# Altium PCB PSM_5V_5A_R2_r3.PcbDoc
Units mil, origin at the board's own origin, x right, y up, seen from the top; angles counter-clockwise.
Board outline 1350 x 1700 mil, 2 copper layers (Top Layer, Bottom Layer), stack 62 mil thick; 44 components, 17 nets, 129 pads, 76 vias.
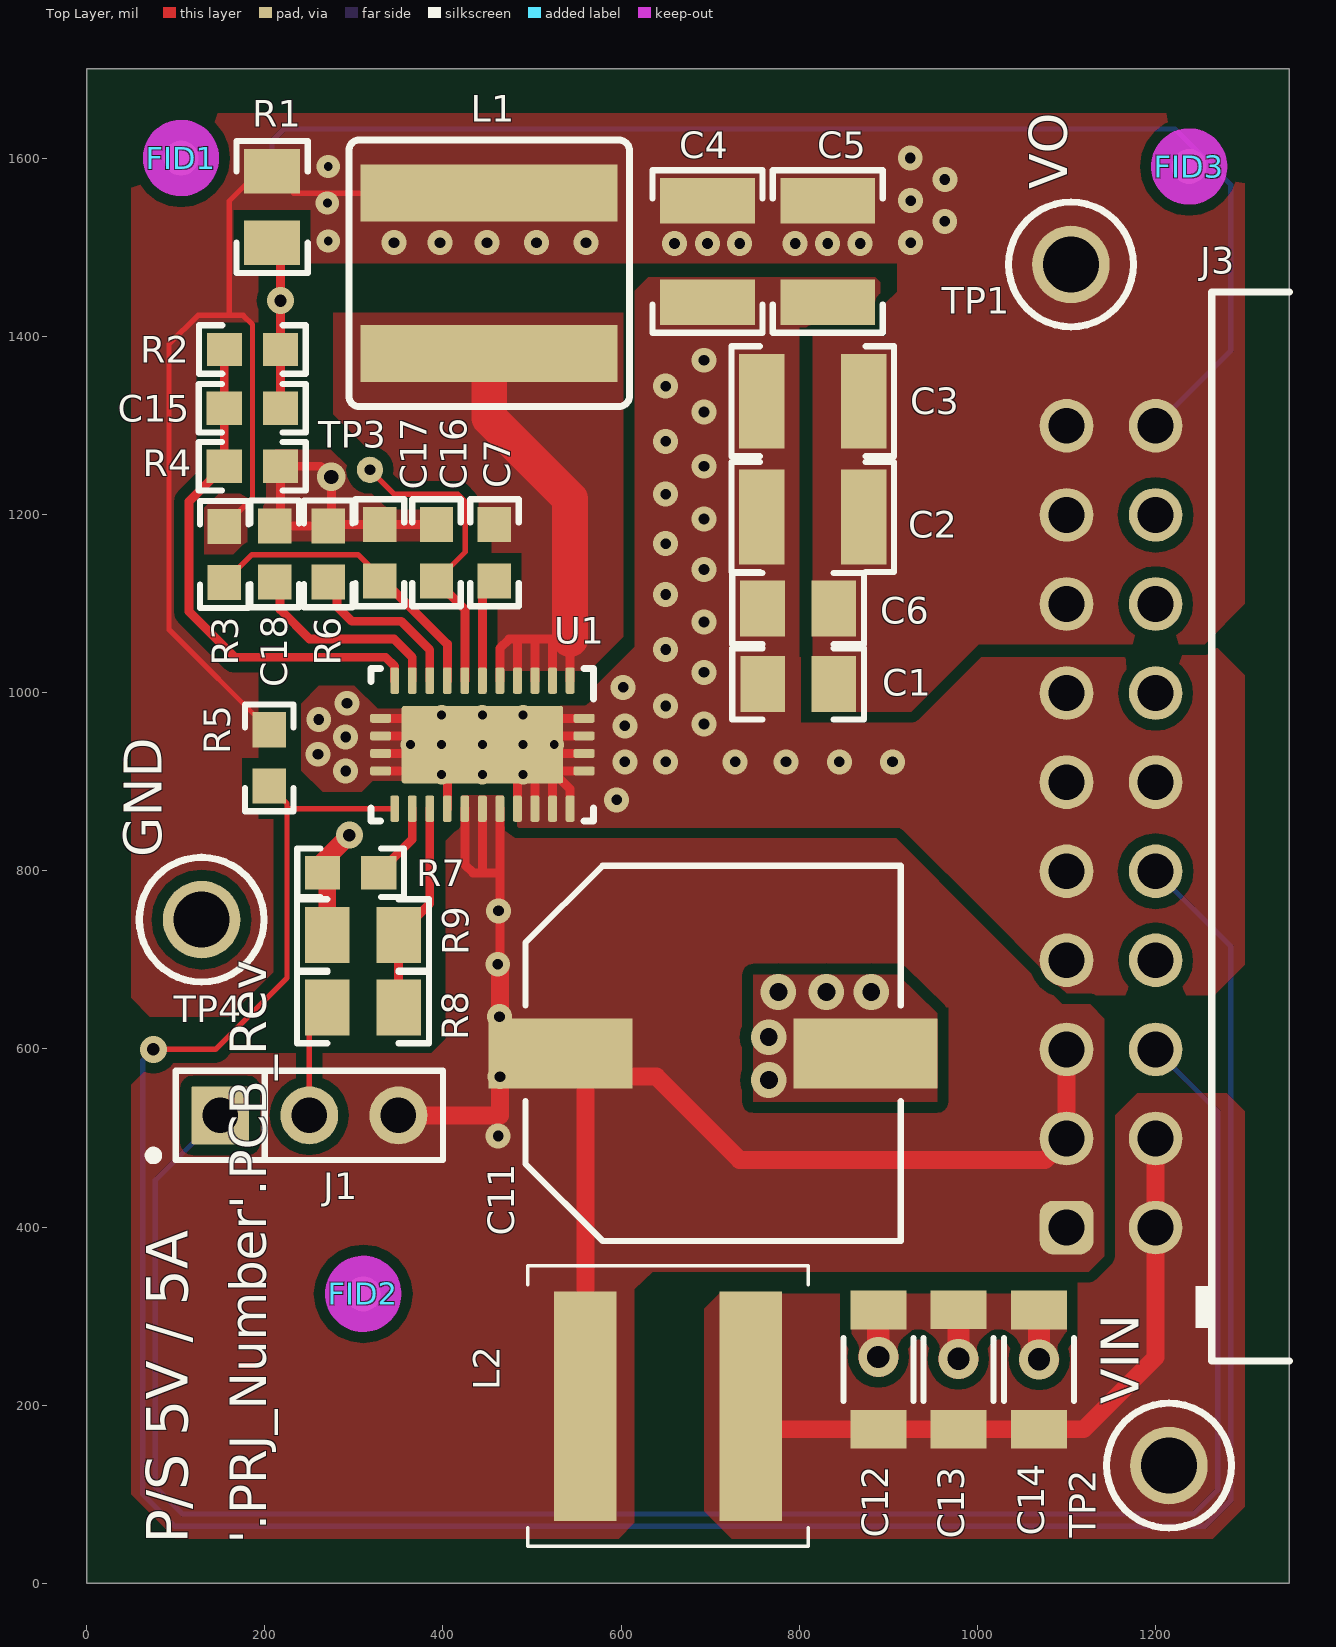
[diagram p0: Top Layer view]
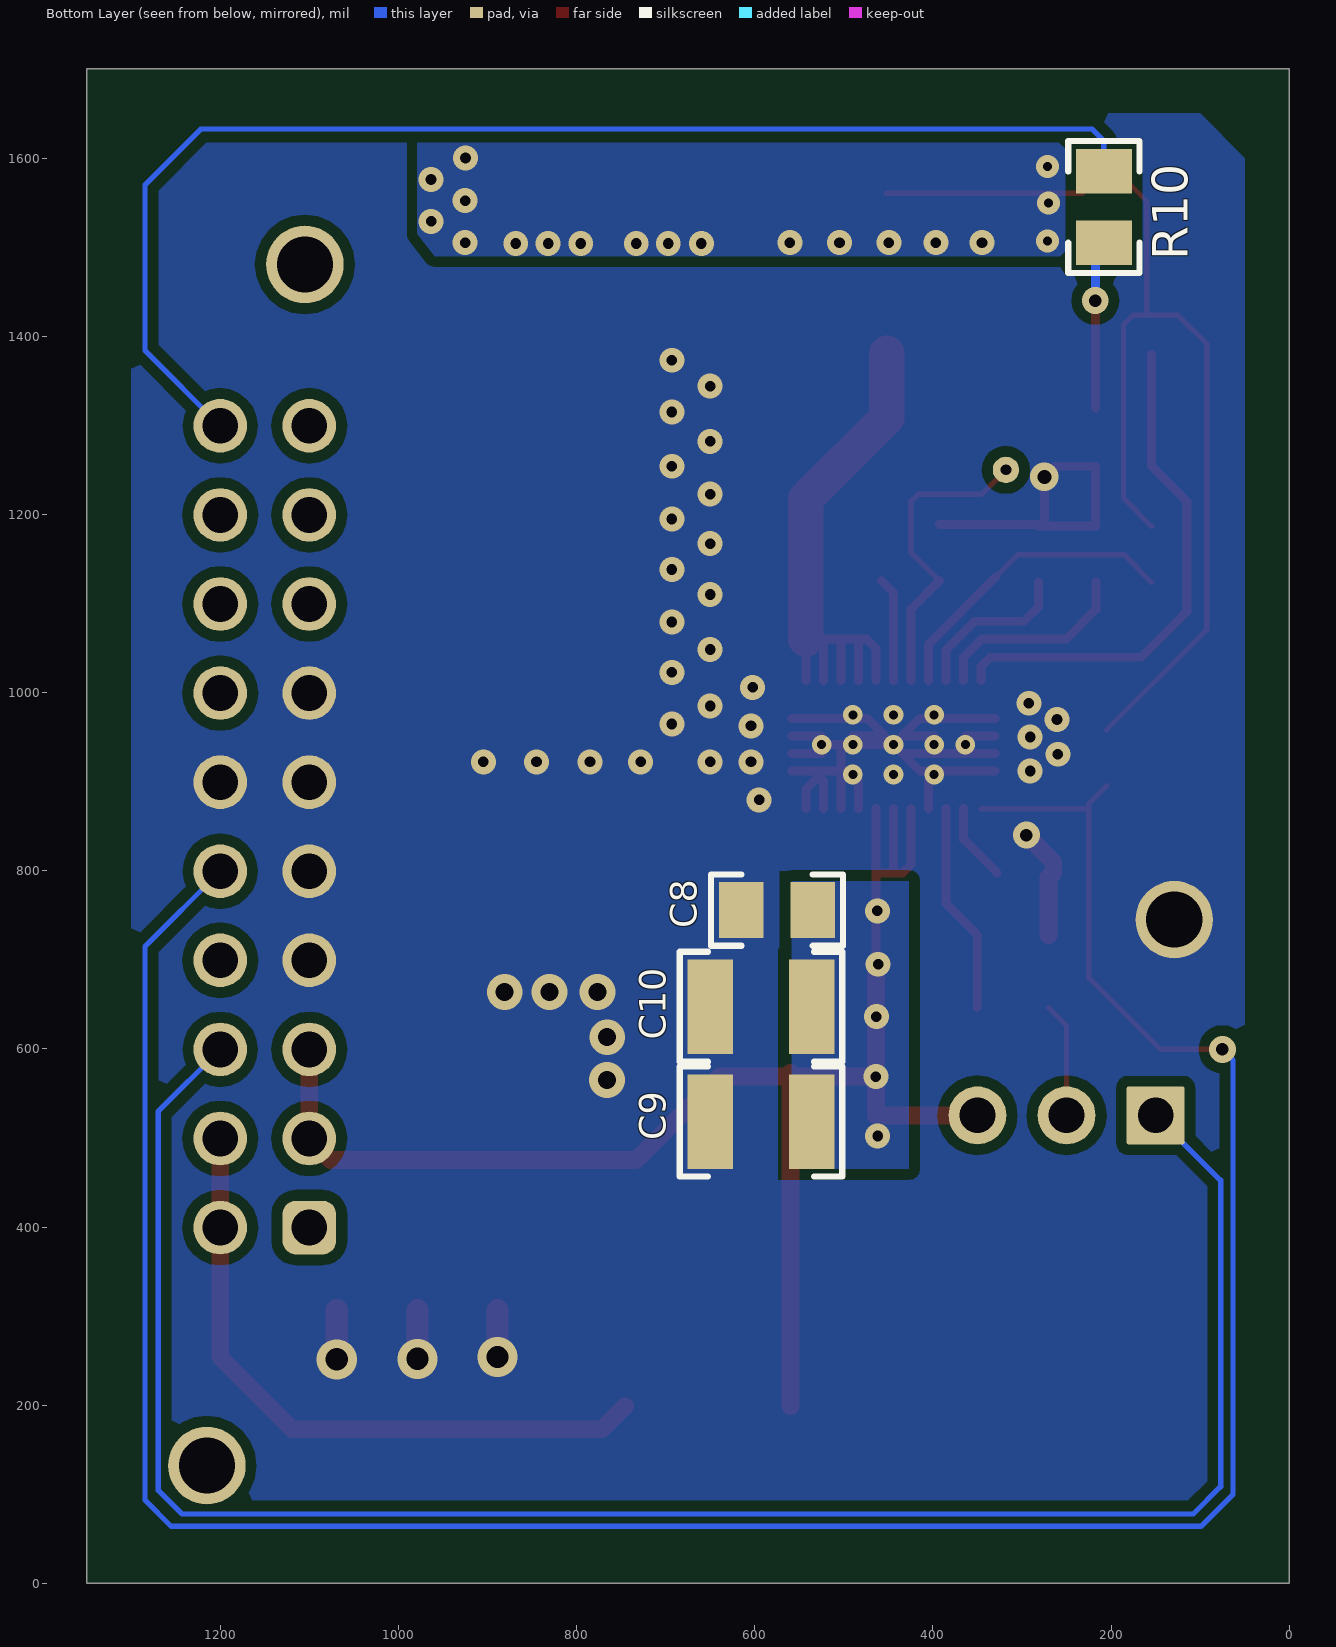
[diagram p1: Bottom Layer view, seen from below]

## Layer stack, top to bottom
Top Solder: solder mask 0.4, Solder Resist, Dk 3.5
Top Layer: signal copper 2.8
Dielectric1: core 56.4, FR-4, Dk 4.8
Bottom Layer: signal copper 2.8
Bottom Solder: solder mask 0.4, Solder Resist, Dk 3.5

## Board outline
0,0 1350,0 1350,1700 0,1700

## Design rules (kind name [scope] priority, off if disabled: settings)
AcuteAngle [All] p1: minimum=4.50000000000000E+0001 checktracksonly=FALSE
AssemblyTestPointUsage [All] p1: valid=2
BoardOutlineClearance BoardOutlineClearance_MountingHoles [OnCopper and InComponentClass('Mounting Holes')] p1: gap=39.37 ignorepadtopadclearanceinfootprint=FALSE
BoardOutlineClearance BoardOutlineClearance_Poly [OnCopper and IsPoly] p2: gap=25 ignorepadtopadclearanceinfootprint=FALSE
BoardOutlineClearance [OnCopper and Not InComponentClass('Logo') and not InComponentClass('FiducialMark') and not InRegion(1000,500,4000,800) and not InPoly] p3: gap=60 ignorepadtopadclearanceinfootprint=FALSE
Clearance Clearance_Keepouts [((IsTrack Or IsArc) And Not InPoly) And IsFree and IsKeepOut vs ((IsTrack Or IsArc) And Not InPoly) And IsFree and IsKeepOut] p1: gap=0 ignorepadtopadclearanceinfootprint=FALSE
Clearance Clearance_Poly [InPolygon] p2: gap=12 ignorepadtopadclearanceinfootprint=TRUE
Clearance Clearance_FiducialMark [IsKeepOut and InComponentClass('FiducialMark') vs IsPad and InComponentClass('FiducialMark')] p3: gap=0 ignorepadtopadclearanceinfootprint=FALSE
Clearance [All] p4: gap=7.87 ignorepadtopadclearanceinfootprint=TRUE
ComponentClearance ComponentClearance_MountingHoles_FiducialMarks [InComponentClass('Mounting Holes') vs InComponentClass('FiducialMark')] p1: gap=50 collisioncheckmode=3 verticalgap=10 showdistances=FALSE
ComponentClearance ComponentClearance_Shunt [InComponentClass('Header') vs InComponentClass('Shunt')] p2: gap=0 collisioncheckmode=3 verticalgap=0 showdistances=FALSE
ComponentClearance ComponentClearance_Logo [InComponentClass('Logo')] p3: gap=50 collisioncheckmode=3 verticalgap=10 showdistances=FALSE
ComponentClearance ComponentClearance_ScrewToNut [(HasFootprint('NY PMS 440 0025 PH')) vs (HasFootprint('Keystone_1902C'))] p4: gap=5 collisioncheckmode=3 verticalgap=10 showdistances=FALSE
ComponentClearance ComponentClearance_MountingHoles [InComponentClass('Mounting Holes')] p5: gap=250 collisioncheckmode=3 verticalgap=100000 showdistances=FALSE
ComponentClearance ComponentClearance_SmallPassives [HasFootprint('0201*') or HasFootprint('0402*') or HasFootprint('0508') or HasFootprint('0603*') or HasFootprint('0612') or HasFootprint('0805*') or HasFootprint('0815*') or HasFootprint('0830*') or HasFootprint('1206*') or HasFootprint('1210*') or HasFootprint('1808*') or HasFootprint('1812*') or HasFootprint('1825*') or HasFootprint('2010*') or HasFootprint('2220*') or HasFootprint('2225*') or HasFootprint('2512*') or HasFootprint('2728*') or HasFootprint('3518*') vs HasFootprint('0201*') or HasFootprint('0402*') or HasFootprint('0508') or HasFootprint('0603*') or HasFootprint('0612') or HasFootprint('0805*') or HasFootprint('0815*') or HasFootprint('0830*') or HasFootprint('1206*') or HasFootprint('1210*') or HasFootprint('1808*') or HasFootprint('1812*') or HasFootprint('1825*') or HasFootprint('2010*') or HasFootprint('2220*') or HasFootprint('2225*') or HasFootprint('2512*') or HasFootprint('2728*') or HasFootprint('3518*')] p6: gap=14.96 collisioncheckmode=3 verticalgap=10 showdistances=FALSE
ComponentClearance ComponentClearance_THtoSMT [IsThruComponent vs IsSMTComponent] p7: gap=40 collisioncheckmode=3 verticalgap=30 showdistances=FALSE
ComponentClearance ComponentClearance_THtoTH [IsThruComponent vs IsThruComponent] p8: gap=30 collisioncheckmode=3 verticalgap=30 showdistances=FALSE
ComponentClearance [All] p9: gap=30 collisioncheckmode=3 verticalgap=10 showdistances=FALSE
DiffPairsRouting [All] p1: maxlimit=100 minlimit=10 mostfreqgap=10 toplayer_minwidth=15 toplayer_maxwidth=15 toplayer_prefwidth=15 bottomlayer_minwidth=15 bottomlayer_maxwidth=15 bottomlayer_prefwidth=15 maxuncoupledlength=1000
FabricationTestPointUsage TestPointUsage [All] p1: valid=2 allowmultiple=FALSE
FabricationTestpoint Testpoint [All] p1: side=3 testpointundercomponent=TRUE minsize=40 maxsize=100 preferedsize=60 minholesize=0 maxholesize=40 preferedholesize=32 testpointgrid=1 allowsidetop=TRUE allowsidebottom=TRUE usegrid=TRUE gridtolerance=0.01
FanoutControl Fanout_LCC [IsLCC] p1: bgadir=Out bgaviamode=Centered fanoutstyle=Auto fanoutdirection=Alternating viagrid=1 // Fanout_LCC (Default Rule)
FanoutControl Fanout_BGA [IsBGA] p2: bgadir=Out bgaviamode=Centered fanoutstyle=Auto fanoutdirection=Alternating viagrid=1 // Fanout_BGA (Default Rule)
FanoutControl Fanout_Default [All] p4: bgadir=Out bgaviamode=Centered fanoutstyle=Auto fanoutdirection=Alternating viagrid=1 // Fanout_Default (Default Rule)
FanoutControl Fanout_Small [(CompPinCount < 5)] p5: bgadir=Out bgaviamode=Centered fanoutstyle=Auto fanoutdirection=OutThenIn viagrid=1 // Fanout_Small (Default Rule)
HoleSize [All] p1: absolutevalues=TRUE maxlimit=251 minlimit=7.87 maxpercent=80.000 minpercent=20.000
MinimumAnnularRing MinimumAnnularRing_ThermalPadVias [IsVia and InAnyComponent] p1: minimumring=5.91
MinimumAnnularRing [All] p2: minimumring=7.87
MinimumSolderMaskSliver MinimumSolderMaskSliver_Logo [InComponentClass('Logo') vs InComponentClass('Logo')] p1: minsoldermaskwidth=0.7
MinimumSolderMaskSliver [All] p2: minsoldermaskwidth=3.94
PlaneConnect [All] p1: planeconnectstyle=Relief reliefexpansion=10 reliefentries=4 reliefconductorwidth=10 reliefairgap=10
PolygonConnect [All] p1: connectstyle=Direct reliefconductorwidth=10 reliefentries=4 polygonreliefangle="90 Angle" airgapwidth=10
RoutingVias ThermalPadVias [IsVia and InAnyComponent] p1: holewidth=7.87 width=19.68 viastyle="Through Hole" minholewidth=7.87 minwidth=19.68 maxholewidth=12.99 maxwidth=23.62
RoutingVias [All] p2: holewidth=16 width=34 viastyle="Through Hole" minholewidth=7.87 minwidth=26 maxholewidth=40 maxwidth=65
SilkToBoardRegionClearance [Not ((IsComment or IsDesignator) And (Hide <> 'False')) and not InRegion(1000,500,4000,800)] p1:
SilkToSilkClearance SilkToSilkClearance_Pb-FreeLogo [(HasFootprint('Pb-Free_Overlay_Medium') OR HasFootprint('Pb-Free_Overlay_Small')) vs (HasFootprint('Pb-Free_Overlay_Medium') OR HasFootprint('Pb-Free_Overlay_Small'))] p1: silktosilkclearance=0
SilkToSilkClearance [All] p2: silktosilkclearance=3.94
SilkToSolderMaskClearance SilkToComponentPadClearance [(IsPad or IsFill or IsRegion) and InAnycomponent] p1: minsilkscreentomaskgap=5 clearancetoexposedcopper=TRUE
SilkToSolderMaskClearance "Silk to Solder Mask Opening" [All] p2: minsilkscreentomaskgap=3.94 clearancetoexposedcopper=FALSE
SolderMaskExpansion [All] p1: expansion=1.97
UnRoutedNet [All] p1: checkbadconnections=TRUE
Width [All] p1: maxlimit=100 minlimit=6 preferedwidth=10 checkconnectedcopper=TRUE
14 further rules are at their usual default settings.

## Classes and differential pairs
component class Header: J1 J6 J7
component class FiducialMark: FID1 FID2 FID3
component class AssemblyNote: ZZ1 ZZ2 ZZ3 ZZ4

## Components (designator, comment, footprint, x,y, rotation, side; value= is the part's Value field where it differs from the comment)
C1 "Capacitor" 0805_HV 798.79,1009.69 r0 top value=0.47uF
C2 "Capacitor" 1210_270 815.05,1197.07 r180 top value=22uF
C3 "Capacitor" 1210_270 815.05,1326.91 r180 top value=22uF
C4 "Capacitor" 1210_270 697.07,1495.02 r270 top value=22uF
C5 "Capacitor" 1210_270 831.91,1495.02 r270 top value=22uF
C6 "Capacitor" 0805_HV 798.72,1094.31 r0 top value=0.47uF
C7 "Capacitor" 0603 457.73,1156.92 r270 top value=0.47uF
C8 "Capacitor" 0805_HV 575,755.84 r180 bottom value=0.47uF
C9 "Capacitor" 1210_270 592.91,518.37 r180 bottom value=10uF
C10 "Capacitor" 1210_270 592.91,647.24 r180 bottom value=10uF
C11 "Cap_Polarized" SM_RADIAL_G 703.2,595 r0 top value=100uF
C12 "Capacitor" 1206_180 888.78,240 r90 top value=2.2uF
C13 "Capacitor" 1206_180 978.61,240.04 r90 top value=2.2uF
C14 "Capacitor" 1206_180 1069.2,240 r90 top value=2.2uF
C15 "Capacitor" 0603 186,1319.13 r180 top value=4.7pF
C16 "Capacitor" 0603 392.73,1156.92 r90 top value=2.2uF
C17 "Capacitor" 0603 329.24,1156.92 r90 top value=1uF
C18 "Capacitor" 0603 211.11,1155.66 r90 top value=0.01uF
FID1 "Fiducial" Fiducial10-20 106.02,1600 r0 top
FID2 "Fiducial" Fiducial10-20 310.59,325 r0 top
FID3 "Fiducial" Fiducial10-20 1237.59,1590.47 r0 top
J1 "Header_3x1" Samtec_HTSW-103-07-G-S 249.99,525.37 r0 top
J3 "SFH11-PBPC-D10-RA-BK" Sullins_SFH11-xxxC-D10-RA 1150,849.41 r90 top
L1 "Inductor_Iron" XAL7070 451.88,1470.62 r90 top value=6.8uH
L2 "Inductor_Iron" XAL7030 652.81,198.94 r0 top value=2.2uH
R1 "Resistor" 0805_HV 208.13,1545 r90 top value=100
R2 "Resistor" 0603 186.15,1385 r0 top value=100k
R3 "Resistor" 0603 154.5,1155 r270 top value=0
R4 "Resistor" 0603 186,1254.04 r180 top value=24.9k
R5 "Resistor" 0603 205,926.73 r270 top value=100k
R6 "Resistor" 0603 271.3,1155.66 r90 top value=100k
R7 "Resistor" 0603 296.41,797.56 r0 top value=100
R8 "RG2012P-222-B-T5" 0805_HV 310.22,646.37 r180 top value=2.20k
R9 "Resistor" 0805_HV 310.22,727.98 r0 top value=121k
R10 "Resistor" 0805_HV 208.13,1545 r90 bottom value=100
TP1 "5013" Keystone5013 1105,1480.52 r0 top
TP2 "5010" Keystone5010 1215,132.3 r0 top
TP3 "TP_H0.45P0.75" TP_H045P075 318.06,1250 r0 top
TP4 "5010" Keystone5010 129.09,745.07 r0 top
U1 "LM73605QRNPRQ1" RNP0030A 444.26,941.47 r270 top
ZZ1 "This Assembly Note is for PCB labels only" AssemblyNoteLabel 185,2313 r0 top
ZZ2 "These assemblies are ESD sensitive, ESD precautions shall be observed." AssemblyNote 185,2204.11 r0 top
ZZ3 "These assemblies must be clean and free from flux and all contaminants. Use of no clean flux is not acceptable." AssemblyNote 185,2115.56 r0 top
ZZ4 "These assemblies must comply with workmanship standards IPC-A-610 Class 2, unless otherwise specified." AssemblyNote 185,2027 r0 top

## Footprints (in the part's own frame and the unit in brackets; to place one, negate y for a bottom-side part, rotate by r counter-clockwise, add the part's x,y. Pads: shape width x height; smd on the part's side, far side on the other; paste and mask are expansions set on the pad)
0603 [mm] "0603 from SM-752 data"
  rect 1x0.95 smd: 1(-0.8,0) 2(0.8,0)
  silkscreen extent -1.52,-0.69 1.52,0.69, body extent -0.87,-0.47 0.87,0.47, height 1
0805_HV [mil] "0805 with 30mil clearance between pads"
  rect 50x63 smd: 1(-40,0) 2(40,0)
  silkscreen extent -74,-40 74,40, body extent -43,-29 43,29, height 57
1206_180 [mm] "1206_180"
  rect 1.1x1.6 smd: 1(-1.7,0) 2(1.7,0)
  silkscreen extent -0.9,-1 0.9,1, body extent -1.75,-0.95 1.75,0.95, height 1.8
1210_270 [mm] "1210"
  rect 1.3x2.7 smd: 1(-1.45,0) 2(1.45,0)
  silkscreen extent -2.32,-1.57 2.32,1.57, body extent -1.7,-1.35 1.7,1.35, height 2.7
AssemblyNote [mil] "Assembly Note"
AssemblyNoteLabel [mil] "Assembly Note for PCB Labels"
Fiducial10-20 [mm]
  round 1 smd mask+0.5: 1(0,0)
  Top Layer keep-out circle w1.178: c0,0 r0.5
Keystone5010 [mil] "Keystone Multipurpose loops"
  round 87 hole 63: 1(0,0)
  silkscreen extent -70,-70 70,70, body extent -63,-63 63,62, height 319
Keystone5013 [mil] "Keystone Multipurpose loops"
  round 87 hole 63: 1(0,0)
  silkscreen extent -70,-70 70,70, body extent -63,-63 63,62, height 319
RNP0030A [mm] "QFN, 30-Leads, Body 6x4mm, Pitch 0.5mm, Thermal Pad 4.6x2.2mm"
  rrect40% 0.75x0.25 smd: 1(-1.825,2.5) 2(-1.825,2) 3(-1.825,1.5) 4(-1.825,1) 5(-1.825,0.5) 6(-1.825,0) 7(-1.825,-0.5) 8(-1.825,-1) 9(-1.825,-1.5) 10(-1.825,-2) 11(-1.825,-2.5) 16(1.825,-2.5) 17(1.825,-2) 18(1.825,-1.5) 19(1.825,-1) 20(1.825,-0.5) 21(1.825,0) 22(1.825,0.5) 23(1.825,1) 24(1.825,1.5) 25(1.825,2) 26(1.825,2.5)
  rrect40% 0.25x0.6 smd: 12(-0.75,-2.9) 13(-0.25,-2.9) 14(0.25,-2.9) 15(0.75,-2.9) 27(0.75,2.9) 28(0.25,2.9) 29(-0.25,2.9) 30(-0.75,2.9)
  rrect5% 2.2x4.6 smd paste-3: 31(0,0)
  rrect10% 0.98x0.96 on Top Paste: 31A(-0.59,1.74) 31A(-0.59,0.58) 31A(-0.59,-0.58) 31A(-0.59,-1.74) 31A(0.59,1.74) 31A(0.59,0.58) 31A(0.59,-0.58) 31A(0.59,-1.74)
  silkscreen extent -2.17,-3.17 2.17,3.18, body extent -2,-3 2,3, height 0.77
Samtec_HTSW-103-07-G-S [mm] "Samtec 100mil, 1x3, 230 mil above insulator"
  rrect6% 1.65x1.65 hole 1.016: 1(-2.54,0)
  round 1.65 hole 1.016: 2(0,0) 3(2.54,0)
  silkscreen extent -4.57,-1.27 3.81,1.27, body extent -3.81,-1.27 3.81,1.27, height 8.38
SM_RADIAL_G [mm] "10 x 10.2mm:  Panasonic G"
  rect 4.1x2 smd: 1(-4.35,0) 2(4.35,0)
  silkscreen extent -5.35,-5.35 5.35,5.35, body extent -5.25,-5.25 5.25,5.25, height 10.5
Sullins_SFH11-xxxC-D10-RA [mm] "Receptacle, 2.54mm, 10x2, R/A, TH"
  rrect50% 1.53x1.53 hole 1.02: 1(-11.43,1.27)
  round 1.53 hole 1.02: 2(-11.43,-1.27) 3(-8.89,1.27) 4(-8.89,-1.27) 5(-6.35,1.27) 6(-6.35,-1.27) 7(-3.81,1.27) 8(-3.81,-1.27) 9(-1.27,1.27) 10(-1.27,-1.27) 11(1.27,1.27) 12(1.27,-1.27) 13(3.81,1.27) 14(3.81,-1.27) 15(6.35,1.27) 16(6.35,-1.27) 17(8.89,1.27) 18(8.89,-1.27) 19(11.43,1.27) 20(11.43,-1.27)
  silkscreen extent -15.24,-5.08 15.24,-2.4, body extent -15.24,-11.37 15.24,1.47, height 7
TP_H045P075 [mm] "TP_H0.45P0.75"
  round 0.75 hole 0.305: 1(0,0)
XAL7030 [mm] "Coilcraft XAL7030 7.5 x.7.5 x 3.1 mm"
  rect 1.78x6.55 smd: 1(-2.36,0) 2(2.36,0)
  silkscreen extent -4,-4 4,4, body extent -4,-4 4,4, height 3.1
XAL7070 [mm] "COILCRAFT"
  rect 1.63x7.33 smd: 1(-2.285,0) 2(2.285,0)
  silkscreen extent -3.8,-4 3.8,4, body extent -3.8,-4 3.8,4, height 7

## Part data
C1 C6 C8: library part CMP-0008357-2, "CAP, CERM, 0.47 uF, 50 V, +/- 10%, X7R, 0805", Cap_Case=0805, Manufacturer=MuRata, PartNumber=GRM21BR71H474KA88L, Supplier Part Number 1=490-3328-1-ND, TempCo=X7R, Tolerance_%=10%, Value1=Unknown, Value2=50V, ValueDisplayed=0.47uF
C2 C3 C4 C5: library part CMP-0009222-2, "CAP, CERM, 22 uF, 16 V, +/- 10%, X7R, 1210", Cap_Case=1210, Manufacturer=MuRata, PartNumber=GRM32ER71C226KE18L, Supplier Part Number 1=490-4524-1-ND, TempCo=X7R, Tolerance_%=10%, Value1="0.003 ohm", Value2=16V, ValueDisplayed=22uF
C7: library part CMP-0007346-5, "CAP, CERM, 0.47 uF, 25 V, +/- 10%, X5R, 0603", Cap_Case=0603, Manufacturer=MuRata, PartNumber=GRM188R61E474KA12D, Supplier Part Number 1=GRM188R61E474KA12D-ND, TempCo=X5R, Tolerance_%=10%, Value1=Unknown, Value2=25V, ValueDisplayed=0.47uF
C9 C10: library part CMP-0009226-3, "CAP, CERM, 10 uF, 50 V, +/- 10%, X7R, 1210", Cap_Case=1210, Manufacturer=MuRata, PartNumber=GRM32ER71H106KA12L, Supplier Part Number 1=490-6544-1-ND, TempCo=X7R, Tolerance_%=10%, Value1=Unknown, Value2=50V, ValueDisplayed=10uF
C11: library part CMP-0011188-2, "CAP, AL, 100 uF, 63 V, +/- 20%, 0.35 ohm, AEC-Q200 Grade 2, SMD", Cap_Case=G, Manufacturer=Panasonic, PartNumber=EEE-FK1J101P, Supplier Part Number 1=PCE3819CT-ND, Tolerance_%=20%, Value1="0.35 ohm", Value2=63V, ValueDisplayed=100uF
C12 C13 C14: library part CMP-0008955-2, "CAP, CERM, 2.2 uF, 50 V, +/- 10%, X5R, 1206", Cap_Case=1206, Manufacturer=MuRata, PartNumber=GRM31CR61H225KA88L, Supplier Part Number 1=GRM31CR61H225KA88L-ND, TempCo=X5R, Tolerance_%=10%, Value1=Unknown, Value2=50V, ValueDisplayed=2.2uF
C15: library part CMP-0006791-4, "CAP, CERM, 4.7 pF, 50 V, +/- 5%, C0G/NP0, 0603", Cap_Case=0603, Manufacturer=AVX, PartNumber=06035A4R7CAT2A, Supplier Part Number 1=478-1159-1-ND, TempCo=C0G/NP0, Tolerance_%=5%, Value1="0.633 ohm", Value2=50V, ValueDisplayed=4.7pF
C16: library part CMP-0007296-4, "CAP, CERM, 2.2 uF, 10 V, +/- 10%, X6S, 0603", Cap_Case=0603, Manufacturer=MuRata, PartNumber=GRM188C81A225KE34D, Supplier Part Number 1=490-4521-1-ND, TempCo=X6S, Tolerance_%=10%, Value1=Unknown, Value2=10V, ValueDisplayed=2.2uF
C17: library part CMP-0006867-4, "CAP, CERM, 1 uF, 25 V, +/- 10%, X7R, 0603", Cap_Case=0603, Manufacturer=Kemet, PartNumber=C0603C105K3RACTU, Supplier Part Number 1=399-7376-1-ND, TempCo=X7R, Tolerance_%=10%, Value1=Unknown, Value2=25V, ValueDisplayed=1uF
C18: library part CMP-0006728-5, "CAP, CERM, 0.01 uF, 100 V, +/- 20%, X7R, 0603", Cap_Case=0603, Manufacturer=AVX, PartNumber=06031C103MAT2A, Supplier Part Number 1=478-3701-1-ND, TempCo=X7R, Tolerance_%=20%, Value1="0.098 ohm", Value2=100V, ValueDisplayed=0.01uF
FID1 FID2 FID3: library part CMP-0077181-1, "Fiducial mark.  There is nothing to buy or mount.", Manufacturer=N/A
J1: library part CMP-0075484-1, "Header, 100mil, 3x1, Gold, TH", Manufacturer=Samtec, PartNumber=HTSW-103-07-G-S, Supplier Part Number 1=HTSW-103-07-G-S-ND
J3: library part CMP-0074634-1, "Receptacle, 2.54mm, 10x2, Gold, R/A, TH", Color=Black, Current_A=3A, Manufacturer="Sullins Connector Solutions", Supplier Part Number 1=S9205-ND, Voltage_V=1kV
L1: library part CMP-0061057-1, "Inductor, Shielded, Composite, 6.8 uH, 9.2 A, 0.02 ohm, SMD", Manufacturer=Coilcraft, PartNumber=XAL7070-682MEB, Value1="0.02 ohm", Value2=9.2A, ValueDisplayed=6.8uH
L2: library part CMP-0061037-1, "Inductor, Shielded, Composite, 2.2 uH, 12.9 A, 0.0137 ohm, SMD", Manufacturer=Coilcraft, PartNumber=XAL7030-222MEB, Value1="0.0137 ohm", Value2=12.9A, ValueDisplayed=2.2uH
R1 R10: library part CMP-0020835-3, "RES, 100, 1%, 0.125 W, AEC-Q200 Grade 0, 0805", Manufacturer=Vishay-Dale, PartNumber=CRCW0805100RFKEA, Power_W=125mW, Supplier Part Number 1=541-100CCT-ND, TempCo="100 ppm/C", Tolerance_%=1%, Value2=0.125W, Value_Code=100R, ValueDisplayed=100
R2 R5 R6: library part CMP-0021990-4, "RES, 100 k, 1%, 0.1 W, AEC-Q200 Grade 0, 0603", Manufacturer=Vishay-Dale, PartNumber=CRCW0603100KFKEA, Power_W=100mW, Supplier Part Number 1=541-100KHCT-ND, TempCo="100 ppm/C", Tolerance_%=1%, Value2=0.1W, Value_Code=100k
R3: library part CMP-0025697-4, "RES, 0, 5%, 0.1 W, AEC-Q200 Grade 0, 0603", Manufacturer=Vishay-Dale, PartNumber=CRCW06030000Z0EA, Power_W=100mW, Supplier Part Number 1=541-0.0GCT-ND, TempCo="200 ppm/C", Tolerance_%=5%, Value2=0.1W, Value_Code=0000, ValueDisplayed=0
R4: library part CMP-0022237-4, "RES, 24.9 k, 1%, 0.1 W, AEC-Q200 Grade 0, 0603", Manufacturer=Vishay-Dale, PartNumber=CRCW060324K9FKEA, Power_W=100mW, Supplier Part Number 1=541-24.9KHCT-ND, TempCo="100 ppm/C", Tolerance_%=1%, Value2=0.1W, Value_Code=24k9, ValueDisplayed=24.9k
R7: library part CMP-0021991-4, "RES, 100, 1%, 0.1 W, AEC-Q200 Grade 0, 0603", Manufacturer=Vishay-Dale, PartNumber=CRCW0603100RFKEA, Power_W=100mW, Supplier Part Number 1=541-100HCT-ND, TempCo="100 ppm/C", Tolerance_%=1%, Value2=0.1W, Value_Code=100R, ValueDisplayed=100
R8: library part CMP-0018920-1, "RES, 2.20 k, 0.1%, 0.125 W, 0805", Manufacturer="Susumu Co Ltd", Power_W=125mW, Supplier Part Number 1=RG20P2.2KBCT-ND, TempCo="25 ppm/C", Tolerance_%=0.1%, Value2=0.125W, Value_Code=2k20, ValueDisplayed=2.20k
R9: library part CMP-0020867-3, "RES, 121 k, 1%, 0.125 W, AEC-Q200 Grade 0, 0805", Manufacturer=Vishay-Dale, PartNumber=CRCW0805121KFKEA, Power_W=125mW, Supplier Part Number 1=541-121KCCT-ND, TempCo="100 ppm/C", Tolerance_%=1%, Value2=0.125W, Value_Code=121k
TP1: library part CMP-0055150-1, "Test Point, Multipurpose, Orange, TH", Color=Orange, Manufacturer=Keystone, Supplier Part Number 1=36-5013-ND
TP2 TP4: library part CMP-0055147-1, "Test Point, Multipurpose, Red, TH", Color=Red, Manufacturer=Keystone, Supplier Part Number 1=36-5010-ND
TP3: library part CMP-0003719-1, "Testpoint", Manufacturer="Texas Instruments"
U1: library part CMP-0013936-4, "Automotive 3.5V to 36V 5A Synchronous Step-Down Voltage Regulator, RNP0030A (WQFN-30)", Alternate Manufacturer="Texas Instruments", Alternate PartNumber=LM73605QRNPTQ1
ZZ1: library part CMP-0003616-3
ZZ2: library part CMP-0077236-1
ZZ3: library part CMP-0077237-1
ZZ4: library part CMP-0077238-1

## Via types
v1: diameter 28, hole 12, Top Layer to Bottom Layer, 50 vias
v2: diameter 22, hole 10, Top Layer to Bottom Layer, 11 vias
v3: diameter 40, hole 20, Top Layer to Bottom Layer, 5 vias
v4: diameter 26, hole 10, Top Layer to Bottom Layer, 3 vias
v5: diameter 30, hole 14, Top Layer to Bottom Layer, 3 vias
v6: diameter 45, hole 25, Top Layer to Bottom Layer, 3 vias
v7: diameter 32, hole 16, Top Layer to Bottom Layer, 1 vias

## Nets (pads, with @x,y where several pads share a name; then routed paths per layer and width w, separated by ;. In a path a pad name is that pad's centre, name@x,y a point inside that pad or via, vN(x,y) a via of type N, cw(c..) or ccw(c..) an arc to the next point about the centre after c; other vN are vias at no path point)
BIAS: C17.1 R3.2 U1.8 | length 345.9
  Top Layer w6: R3.2 185.72,1154.72 304.46,1154.72 C17.1@329.24,1129.94
  Top Layer w10: C17.1@329.24,1129.94 404.89,1054.3 U1.8
EN: R8.1 R9.2 U1.18 | length 237.7
  Top Layer w10: R8.1 R9.2 385.2,762.96 U1.18
EN-EXT: J1.1 J3.6 | length 2187.1
  Bottom Layer w6: J1.1 77.04,452.41 77.04,108.55 107.75,77.84 1242.82,77.84 1269.71,104.73 1269.71,529.71 J3.6
FB: C15.2 R2.1 R4.2 U1.11 | length 577.3
  Top Layer w10: R2.1@154.5,1379.49 C15.2 R4.2 115,1214.54 115,1090.8 166.18,1039.62 335.52,1039.62 345.83,1029.31 U1.11
GND: C1.1 C2.2 C3.2 C4.2 C5.2 C6.1 C8.1 C9.1 C10.1 C11.2 C12.2 C13.2 C14.2 C16.2 C17.2 C18.2 J3.7 J3.9 J3.11 J3.12 J3.13 R4.1 R6.2 R7.1 R9.1 TP4.1 U1.12 U1.13 U1.14 U1.15 U1.19 U1.23 U1.24 U1.25 U1.26 U1.27 U1.28 U1.29 U1.30 U1.31 | length 1648.3
  Top Layer w10: R6.2@281.3,1187.15 R6.2 217.11,1187.15 217.49,1187.54 R4.1 262.76,1254.04 v7(274.76,1242.04) 274.76,1190.25 276.59,1188.42 C17.2 C16.2 ; U1.15 414.73,911.95 U1.31@434.42,931.63 ; U1.14 U1.31@434.42,931.63 ; U1.13 U1.31@363.55,951.32 ; U1.12 414.73,971 434.42,951.32 U1.31@398.59,951.32 ; U1.19 U1.31@404.89,902.1 ; U1.23 U1.31@483.63,902.1 ; U1.31@489.93,911.95 U1.31@503.31,911.95 ; U1.31@489.93,951.32 454.1,951.32 473.79,971 U1.30 ; U1.24 U1.31@503.31,911.95 ; U1.31@503.31,937.59 U1.31@503.31,911.95 ; U1.31@515.12,941.47 v2(489.93,941.47) v2(444.26,941.47) U1.31@434.42,931.63 ; U1.25 U1.31@523,900.51 ; U1.31@524.97,931.63 U1.28 ; U1.31@524.97,951.32 U1.29 ; U1.26 542.68,891.51 524.97,909.23 U1.31@524.97,911.95 ; U1.27 U1.31@524.97,911.95 ; U1.31@503.31,911.95 U1.31@524.97,911.95
  Top Layer w20: R9.1 270.22,792.25 R7.1 264.91,809.91 v5(295,840)
  Top Layer w25: C12.2 v6(888.78,254.2) v6@892.98,250 ; C13.2 v6(978.61,252.06) v6@981.74,248.94 ; C14.2 v6(1069.2,251.47) v6@1071.74,248.94
  other v1: 595,879.62 290.87,911.95 604.16,922.25 650,922.25 728.03,922.25 785,922.25 845,922.25 904.66,922.25 259.79,930.73 290.86,950 604.16,962.62 693.07,964.7 260.61,969.8 650,985 292.32,988 602.3,1005.88 693.07,1022.62 650,1048.42 693.07,1079.26 650,1110.1 693.07,1138.17 650,1167.12 693.07,1194.9 650,1222.62 693.07,1254.02 650,1282.01 693.07,1315 650,1343.89 693.07,1373
  other v2: 398.59,908.01 444.26,908.01 489.93,908.01 363.55,941.47 398.59,941.47 524.97,941.47 398.59,974.94 444.26,974.94 489.93,974.94
  other v3: 765.83,565 765.69,613.22 776.53,663.82 830.45,663.82 880.73,663.82
NetC7_2: C7.2 U1.6 | length 117.7
  Top Layer w10: U1.6 444.26,1111.95 C7.2
NetC15_1: C15.1 R1.1 R2.2 R10.1 | length 258.8
  Top Layer w10: R1.1 217.64,1495.48 v5(217.64,1440) R2.2 217.49,1384.85 C15.1
  Bottom Layer w10: R10.1 217.64,1495.48 v5(217.64,1440)
NetJ1_2: J1.2 R8.2 | length 129.4
  Top Layer w6: J1.2 249.99,626.14 R8.2
PGOOD: J3.10 R5.2 U1.16 | length 3021.6
  Top Layer w6: v5(75,599.41) 144.65,599.41 225,679.76 225,869.62 ; R5.2 225,875.24 225,869.62 ; U1.16 225,869.62
  Bottom Layer w6: v5(75,599.41) 63.16,587.58 63.16,100.01 99.21,63.97 1255.01,63.97 1284.46,93.42 1284.46,714.95 J3.10
RT: R6.1 U1.9 | length 186.4
  Top Layer w10: R6.1@281.3,1124.16 281.3,1096.44 297.74,1080 353.19,1080 385.2,1047.98 U1.9
SS/TRK: C18.1 U1.10 | length 227.8
  Top Layer w10: C18.1@217.11,1124.16 217.11,1093.26 250.37,1060 345.14,1060 365.52,1039.62 U1.10
SW: C7.1 L1.1 U1.1 U1.2 U1.3 U1.4 U1.5 | length 666.9
  Top Layer w10: U1.5 463.94,1049.69 474.26,1060 485,1060 ; U1.4 483.63,1058.63 485,1060 ; U1.3 503.31,1058.31 505,1060 ; U1.2 523,1057 520,1060 ; U1.1 542.68,1060 520,1060 ; 485,1060 505,1060 ; 505,1060 520,1060
  Top Layer w40: L1.1 451.88,1308.22 542.68,1217.42 542.68,1060
SYNC: R7.2 U1.17 | length 87.6
  Top Layer w10: R7.2 365.52,835.17 U1.17
VCC: C16.1 TP3.1 U1.7 | length 349.2
  Top Layer w6: TP3.1 345.67,1222.4 416.82,1222.4 425,1214.22 425,1157.69 C16.1
  Top Layer w10: C16.1 424.57,1093.59 U1.7
VIN: C8.2 C9.2 C10.2 C11.1 J1.3 J3.1 J3.3 J3.5 L2.1 U1.20 U1.21 U1.22 | length 1795.3
  Top Layer w10: U1.20 424.57,806.94 433.96,797.56 445,797.56 ; U1.21 444.26,798.3 445,797.56 ; v1@463.94,687.53 463.94,797.56 ; U1.22 463.94,797.56 ; 445,797.56 463.94,797.56
  Top Layer w20: J1.3 463.94,525.37 C11.1@463.94,568.87 ; v1@463.94,687.53 C11.1@463.94,568.87 ; L2.1 C11.1@559.89,568.87 ; C11.1@559.89,572.95 C11.1@559.89,568.87 ; J3.5 J3.3 1075.96,475.37 733.05,475.37 639.55,568.87 C11.1@559.89,568.87 ; C11.1@463.94,568.87 C11.1@559.89,568.87
  other v1: 462,502.24 464,568.87 463.52,636.2 461.52,695 462.43,755
VIN_EMI: C12.1 C13.1 C14.1 J3.2 J3.4 L2.2 TP2.1 | length 744
  Top Layer w20: L2.2 771.59,173.07 C12.1 C14.1 1119.2,173.07 1200,253.87 J3.2 J3.4
VOS_P: C1.2 C2.1 C3.1 C4.1 C5.1 C6.2 J3.15 J3.17 J3.19 J3.20 L1.2 R1.2 R3.1 R5.1 R10.2 TP1.1 | length 2721.6
  Top Layer w6: R3.1 186.15,1218.14 186.15,1412.98 175.66,1423.47 160,1423.47 ; R5.1 92.55,1070.68 92.55,1391.05 124.97,1423.47 160,1423.47 ; L1.2 232.54,1560.59 R1.2 193.51,1585 160,1551.49 160,1423.47
  Bottom Layer w6: R10.2 208.13,1619 221.66,1632.54 1221.81,1632.54 1284.46,1569.88 1284.46,1383.87 J3.20
  other v1: 660,1504 697.07,1504 733.03,1504 795.32,1504 831.91,1504 868.3,1504 345,1505 396.72,1505 449.42,1505 504.93,1505 560.67,1505 925,1505 963.28,1529 925,1552.1 963.38,1576 924.58,1600
  other v4: 271.22,1507 270.22,1549.34 271.3,1590.47
pads on no net: FID1.1 FID2.1 FID3.1 J3.8 J3.14 J3.16 J3.18 U1.31A

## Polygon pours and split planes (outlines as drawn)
VIN on Bottom Layer "BOTTOM_LAYER_VIN_P038" (solid, remove dead copper, pour order 38): 426.91,465.22 559.67,465.22 558.43,466.46 558.43,788.42 426.91,788.42
VOS_P on Bottom Layer "BOTTOM_LAYER_VOS_P_P039" (solid, remove dead copper, pour order 39): 257.22,1489.89 912.57,1489.89 959.45,1489.89 978.61,1514.86 978.61,1617.24 258.71,1617.24 251.63,1610.16 251.63,1495.48
GND on Bottom Layer "BOTTOM_LAYER_GND_P041" (solid, remove dead copper, pour order 41): 50,94.7 94.7,50 1250,50 1300,100 1300,1600 1250,1650 100,1650 50,1600
VIN on Top Layer "TOP_LAYER_VIN_P053" (solid, remove dead copper, pour order 53): 412.35,620.52 386.82,595 85,595 50,560 50,100.01 100,50.15 413.1,50.15
GND on Top Layer "TOP_LAYER_GND_P052" (solid, remove dead copper, pour order 52): 198.43,1183.71 212.13,1170 410,1170 410,1207.33 339.71,1207.18 274.16,1272.74 202.06,1272.74 198.41,1269.09
VOS_P on Top Layer "TOP_LAYER_VOS_P_P051" (solid, remove dead copper, pour order 51): 320.7,1650 290.23,1650 100,1650 50,1600 50,657.33 71.13,636.2 163.22,636.2 215,687.98 215,857.6 192.45,857.6 192.45,1482.05 927.05,1482.05 985.02,1540.02 320.7,1540.02
GND on Top Layer "TOP_LAYER_GND_P050" (solid, remove dead copper, pour order 50): 363.55,981.61 326.59,981.61 314.22,993.99 300.64,1007.57 260.87,1007.57 240.98,987.68 240.98,912.46 264.98,888.47 309.05,888.47 321.42,900.83 363.55,900.43
GND on Top Layer "TOP_LAYER_GND_P042" (solid, remove dead copper, pour order 42): 910.47,683.24 748.24,683.24 748.24,540.45 954.73,540.45 954.73,640
GND on Top Layer "TOP_LAYER_GND_P049" (solid, remove dead copper, pour order 49): 858.64,325 858.64,236.8 876.99,218.45 1094.44,218.45 1110.99,235.01 1110.99,325
GND on Top Layer "TOP_LAYER_GND_P048" (solid, remove dead copper, pour order 48): 780.56,1009.12 800,1028.56 800,1410 893.58,1410 910,1426.42 910,1448.29 892.26,1466.03 630.36,1466.03 615.38,1451.05 615.38,1051.38 573.12,1009.12
VIN_EMI on Top Layer "TOP_LAYER_VIN_EMI_P047" (solid, remove dead copper, pour order 47): 693.07,80.9 723.97,50 1264.11,50 1300,85.89 1300,530 1280,550 1179.35,550 1150,520.65 1150,375 1100,325 710,325 693.07,308.07
GND on Top Layer "TOP_LAYER_GND_P046" (solid, remove dead copper, pour order 46): 483.63,902.1 483.63,842.83 490.25,836.2 594.12,836.2 888.82,836.2 1064.95,660.06 1265.58,660.06 1300,694.48 1300,1019.46 1269.5,1049.96 1174.96,1049.96 1164.62,1039.62 603.62,1039.62 569.26,1005.26 569.26,992.65 560,985 531.94,985
VIN on Top Layer "TOP_LAYER_VIN_P045" (solid, remove dead copper, pour order 45): 1095,650 1005,740 908.8,836.2 594.12,836.2 481.35,836.2 469.39,845 469.39,884.76 419.64,884.76 419.7,850.13 403.06,833.49 403.06,50.15 597.2,50.15 614.91,67.87 614.91,330 635.35,350 1125,350 1142.48,367.48 1142.48,633.87 1126.35,650
SW on Top Layer "TOP_LAYER_SW_P043" (solid, remove dead copper, pour order 43): 463.94,1023.32 465.19,1024.57 564.33,1024.57 602.3,1062.54 602.3,1426.45 276.59,1426.45 276.59,1312.3 361.16,1227.73 413.3,1227.73 455,1186.84 455,1023.32
VOS_P on Top Layer "TOP_LAYER_VOS_P_P044" (solid, remove dead copper, pour order 44): 306.21,1649.64 306.21,1530 913.83,1530 913.83,1650 306.63,1650
VOS_P on Top Layer "TOP_LAYER_VOS_P_P040" (solid, remove dead copper, pour order 40): 1300,1099.41 1300,1600 1250,1650 910,1650 910,1450 873.75,1415 815,1415 815,990.52 827.02,978.5 925.93,978.5 1001.73,1054.3 1254.88,1054.3

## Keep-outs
Keep-Out Layer:
  text ".Layer_Name" at 577,-858.49 h60

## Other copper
Top Layer:
  text ".Layer_Name" at 577,-858.49 h60
Bottom Layer:
  pour cut-out: 20,620
  pour cut-out: 0,652.24
  text ".Layer_Name" at 577,-858.49 h60

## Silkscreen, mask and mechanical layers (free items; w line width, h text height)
Top Overlay:
  text "VO" at 1115,1565 h72.83 r90
  text "GND" at 98.58,815 h72.83 r90
  text "VIN" at 1195,201.01 h72.83 r90
  text "P/S 5V / 5A" at 129.09,44.34 h80 r90
  text "'.PRJ_Number'.PCB_Rev" at 215.11,44.34 h70 r90
  text ".Layer_Name" at 577,-858.49 h60
Bottom Overlay:
  text ".Layer_Name" at 577,-858.49 h60
Top Paste:
  text ".Layer_Name" at 577,-858.49 h60
Bottom Paste:
  text ".Layer_Name" at 577,-858.49 h60
Top Solder:
  text ".Layer_Name" at 577,-858.49 h60
  text ".Layer_Name" at 577,-858.49 h60
Bottom Solder:
  text ".Layer_Name" at 577,-858.49 h60
Drill Guide:
  text ".Layer_Name" at 577,-858.49 h60
M1 Board Outline:
  the board outline again, w10
  text ".Layer_Name" at 577,-858.49 h60
M2 Board Dimensions:
  rectangle: 0,-275 125,-150
  rectangle: 125,-400 500,-275
  lines w7: 0,-275 1000,-275 ; 125,-400 125,-150 ; 250,-400 250,-150 ; 500,-400 500,-150 ; 750,-400 750,-150 ; 0,-400 1000,-400 1000,-150 0,-150 0,-400
  text ".Layer_Name" at 577,-858.49 h60
M3 3D STEP Top:
  text ".Layer_Name" at 577,-858.49 h60
M4 3D STEP Bottom:
  text ".Layer_Name" at 577,-858.49 h60
M5 Assembly Top:
  lines w10: -292,-930.17 6308,-930.17 ; -292,-726.83 6310,-726.83 ; -292,-523.5 -292,-1133.5 3713,-1133.5 6310,-1133.5 6310,-523.5 -291.5,-523.5 -291.5,-1133.5 1284,-1133.5 ; 2173,-1133.5 2173,-523.5 ; 3440,-726.83 3440,-523.5 ; 4280,-726.83 4280,-523.5 ; 4902,-1140 4902,-937.17
  text "COMPONENTS MARKED 'DNP' SHOULD NOT BE POPULATED." at 1153.5,-318.5 h60
  text "ASSEMBLY VARIANT:" at 1153,-434 h60
  text ".VariantName" at 2189,-434 h60
  text "PCB VIEWED FROM TOP SIDE" at -228.5,-655.67 h60
  text "BOARD #:" at 2248,-655.67 h60
  text ".PRJ_Number" at 2793.5,-655.67 h60
  text "REV:" at 3638,-655.67 h60
  text ".PCB_Rev" at 3929.5,-655.67 h60
  text "SVN REV:" at 4476,-655.67 h60
  text ".VersionControl_RevNumber" at 4982,-655.67 h60
  text "TID #:" at 2248,-859 h60
  text ".TID" at 2793.5,-859 h60
  text "PLOT NAME =" at -228.5,-1064.34 h60
  text ".plot_File_Name" at 577,-1064.34 h60
  text "GENERATED    :" at 2250,-1064.34 h60
  text ".Print_Date" at 3119.5,-1064.34 h60
  text ".Print_Time" at 3848.5,-1064.34 h60
  text "TEXAS INSTRUMENTS" at 5113,-1064.34 h60
M6 Assembly Bottom:
  lines w10: -292.5,-727.33 6309.5,-727.33 ; -290.5,-930.67 6309.5,-930.67 ; 1115.5,-1140.5 1115.5,-937.67 ; 1737.5,-727.33 1737.5,-524 ; 2577.5,-727.33 2577.5,-524 ; 3844.5,-1134 3844.5,-524 ; 4733.5,-1134 6309,-1134 6309,-524 -292.5,-524 -292.5,-1134 2304.5,-1134 6309.5,-1134 6309.5,-524
  text "COMPONENTS MARKED 'DNP' SHOULD NOT BE POPULATED." at 6102,-318 h60
  text ".VariantName" at 5058,-434 h60
  text "ASSEMBLY VARIANT:" at 6097,-434 h60
  text ".VersionControl_RevNumber" at 1035.5,-656.17 h60
  text "SVN REV:" at 1541.5,-656.17 h60
  text ".PCB_Rev" at 2088,-656.17 h60
  text "REV:" at 2379.5,-656.17 h60
  text ".PRJ_Number" at 3224,-656.17 h60
  text "BOARD #:" at 3769.5,-656.17 h60
  text "PCB VIEWED FROM BOTTOM SIDE" at 6246,-656.17 h60
  text ".TID" at 3224,-859.5 h60
  text "TID #:" at 3769.5,-859.5 h60
  text "TEXAS INSTRUMENTS" at 904.5,-1064.84 h60
  text ".Print_Time" at 2169,-1064.84 h60
  text ".Print_Date" at 2898,-1064.84 h60
  text "GENERATED    :" at 3767.5,-1064.84 h60
  text ".plot_File_Name" at 5440.5,-1064.84 h60
  text "PLOT NAME =" at 6246,-1064.84 h60
M9 Title Sheet:
  drawing of 57 lines, arcs and shapes, not listed
  text "1" at 739.84,8036.5 h70
  text "2" at 3235.5,8036.5 h70
  text "3" at 5724.84,8036.5 h70
  text "4" at 8231.51,8036.5 h70
  text "5" at 10730.5,8036.5 h70
  text "6" at 13235.5,8036.5 h70
  text "A" at -416.5,6893.5 h70
  text "A" at 14383.5,6893.5 h70
  text "B" at -416.5,4513.5 h70
  text "B" at 14383.5,4513.5 h70
  text "C" at -416.5,2138.5 h70
  text "C" at 14383.5,2138.5 h70
  text "PROJECT TITLE:" at 11343.5,277.5 h45
  text ".PRJ_Title" at 11393.5,144.17 h70
  text "DESIGNED FOR:" at 11343.5,-23.5 h45
  text ".PRJ_Customer" at 11393.5,-163.5 h70
  text "D" at -416.5,-231.5 h70
  text "D" at 14383.5,-231.5 h70
  text "FILE NAME:" at 11343.5,-323.5 h45
  text ".PCB_File_Name_No_Path" at 11393.5,-443.5 h70
  text "Texas Instruments (TI) and/or its licensors do not warrant the accuracy or completeness of this specification" at 6374,-605.34 h45
  text "ENGINEER:" at 11343.5,-613.5 h45
  text "LAYOUT BY:" at 12848.5,-613.5 h45
  text "or any information contained therein. TI and/or its licensors do not warrant that this design will meet" at 6329.01,-718 h45
  text ".PRJ_Engineer" at 11393.5,-768.49 h70
  text ".PCB_Layout" at 12899,-768.49 h70
  text "the specifications, will be suitable for your application or fit for any particular purpose, or will operate in" at 6329.01,-830.67 h45
  text ".Layer_Name" at 577,-858.49 h60
  text "ALTIUM DESIGNER VERSION:" at 12848.5,-923.5 h45
  text "an implementation. TI and/or its licensors do not warrant that the design is production worthy. You should" at 6329.01,-943.33 h45
  text "completely validate and test your design implementation to confirm the system functionality for your application." at 6374,-1056 h45
  text ".print_Scale" at 11393.5,-1056.83 h70
  text ".Application_BuildNumber" at 12899,-1056.83 h70
  text "1" at 739.84,-1263.5 h70
  text "2" at 3235.5,-1263.5 h70
  text "3" at 5724.84,-1263.5 h70
  text "4" at 8231.51,-1263.5 h70
  text "5" at 10730.5,-1263.5 h70
  text "6" at 13235.5,-1263.5 h70
M10 Fab Notes:
  drawing of 189 lines, arcs and shapes, not listed
  text "DESIGN INFORMATION" at 12382.02,6356.17 h60
  text "MIN. TRACK WIDTH:" at 11737.46,6224.05 h60
  text "8" at 12833.7,6224.05 h60
  text "MIL" at 12988.46,6224.05 h60
  text "MIN. CLEARANCE:" at 11737.46,6099.92 h60
  text "0.2" at 12773.7,6099.93 h60
  text "mm" at 12988.46,6099.92 h60
  text "MIN. VIA PAD SIZE:" at 11737.46,5975.8 h60
  text "24" at 12803.71,5975.8 h60
  text "MIL" at 12988.46,5975.8 h60
  text "0.05mm (2MIL)" at 12432.46,5845.9 h60
  text "MINIMUM ANNULAR RING" at 11408.23,5837.67 h60
  text "EXTERNAL" at 13140.46,5837.67 h60
  text "PER" at 11608.23,5727.55 h60
  text "IPC-D-275 CLASS 2 LEVEL C" at 11828.23,5727.54 h60
  text "MIL, HOLES" at 13316.46,5627.07 h60
  text "+/-" at 12924,5618.48 h60
  text "+/-" at 13778,5618.48 h60
  text "REGISTRATION TOLERANCES:" at 11408.23,5617.42 h60
  text "METAL" at 12608,5617.42 h60
  text "5" at 13184.2,5617.42 h60
  text "3" at 14017.2,5617.42 h60
  text "MIL" at 14133.46,5617.42 h60
  text "HOLE SIZE TOLERANCE (UNLESS OTHERWISE SPECIFIED):" at 11408.23,5519.1 h60
  text "+/-" at 13778,5516.23 h60
  text "3" at 14017.2,5515.17 h60
  text "MIL" at 14133.46,5515.17 h60
  text "MATERIAL:" at 11333.46,5377.52 h60
  text "FR-4 High Tg" at 12319.9,5249 h60
  text "X" at 12175.46,5241.01 h60
  text "FR-408" at 11754.46,5236.49 h60
  text "OTHER" at 13242.46,5236.49 h60
  text "62 MIL (1.6mm) +/-10%" at 12074.56,5093.46 h60
  text "X" at 11954.46,5091.01 h60
  text "THICKNESS:" at 11408.23,5085.24 h60
  text "OTHER" at 13359.46,5085.24 h60
  text "TOLERANCE:" at 11408.23,4946.92 h60
  text "X" at 12256.46,4946.92 h60
  text "ANSI IPC-6012 TYPE 3 CLASS 2" at 12434.48,4946.92 h60
  text "OTHER +/-" at 12434.46,4802.73 h60
  text "BOW & TWIST:" at 11408.23,4657.54 h60
  text "X" at 12256.46,4657.54 h60
  text "ANSI IPC-6012 TYPE 3 CLASS 2" at 12434.48,4657.54 h60
  text "OTHER +/-" at 12434.46,4510.85 h60
  text "DRILLING:" at 11333.46,4380.23 h60
  text "NC_DRILL FILES" at 13094.46,4275.04 h60
  text "REFERENCE:" at 11408.23,4271.1 h60
  text "X" at 12065.46,4271.01 h60
  text "AS SHOWN" at 12243.46,4271.1 h60
  text "X" at 12966.46,4271.1 h60
  text "OTHER" at 13392.46,4128.85 h60
  text "PTH COPPER THICKNESS:" at 11407.91,4125.32 h60
  text "X" at 12547.14,4125.32 h60
  text "20-30 um" at 12675.14,4125.32 h60
  text "BOARD FINISH:" at 11333.46,3977.73 h60
  text "SILKSCREEN:" at 11488.68,3867.6 h60
  text "X" at 12446.46,3867.6 h60
  text "TOP" at 12563.46,3867.6 h60
  text "X" at 12956.46,3867.6 h60
  text "BOTTOM" at 13074.46,3867.6 h60
  text "SILKSCREEN COLOR:" at 11488.68,3712.41 h60
  text "X" at 12445.46,3712.41 h60
  text "WHITE" at 12563.46,3712.41 h60
  text "OTHER" at 13074.46,3712.41 h60
  text "X" at 12576.46,3568.96 h60
  text "GREEN" at 12694.46,3568.96 h60
  text "OTHER" at 13312.46,3568.96 h60
  text "SOLDER RESIST COLOR:" at 11488.68,3562.1 h60
  text "X" at 12576.46,3414.71 h60
  text "MATTE" at 12694.46,3414.71 h60
  text "SEMI-GLOSS" at 13312,3414.07 h60
  text "IMMERSION GOLD (ENIG)" at 12394.46,3241.94 h60
  text "ENEPIG" at 13732,3234.72 h60
  text "SURFACE FINISH:" at 11333.46,3233.72 h60
  text "IMM. TIN/SILVER OR EQUIV" at 11663,3096.4 h60
  text "X" at 11510,3095 h60
  text "OTHER" at 13094.46,3092.47 h60
  text "ARRAY/PANEL:" at 11333.46,2937.09 h60
  text "CUT AND TRIM PER M1 BOARD OUTLINE" at 12394.46,2928.87 h60
  text "N.C. ROUTE" at 12394.46,2792.9 h60
  text "X" at 13082.46,2792.9 h60
  text "V. SCORE" at 13260.46,2792.9 h60
  text "CERTIFICATION:" at 11333.46,2663.77 h60
  text "MATERIALS AND WORKMANSHIP FOR ALL PCBS" at 12058.46,2663.77 h60
  text "TO MEET OR EXCEED THE REQUIREMENTS OF:" at 12058.46,2569.71 h60
  text "X" at 11695.97,2441.08 h60
  text "ANSI IPC-A-600F CLASS ->" at 11823.96,2441.08 h60
  text "X" at 13471.97,2441.08 h60
  text "2" at 13581.96,2441.08 h60
  text "1" at 13266.96,2439.58 h60
  text "3" at 13935.96,2439.58 h60
  text "X" at 12507.97,2293.39 h60
  text "RoHS" at 12635.96,2293.39 h60
  text "OTHER" at 13280.36,2293.39 h60
  text "PER ORDER" at 13677.42,2293.39 h60
  text "ALL BOARDS MUST MEET OR EXCEED UL94-V0 REQUIREMENTS." at 11361,2139.57 h60
  text "PCB MUST BEAR THE UL94V-0 UL REGISTERED MATERIAL ID NUMBER" at 11361,2023.5 h60
  text "ADDITIONAL REQUIREMENTS:" at 11333.46,1854.08 h60
  text "MICROSECTION:" at 11408.23,1746.95 h60
  text "YES" at 12313.96,1746.95 h60
  text "REQUIRED" at 13175.46,1602.62 h60
  text "BARE BOARD ELEC. TEST:" at 11408.23,1599.76 h60
  text "NONE" at 12713.96,1599.76 h60
  text "X" at 13057.46,1599.76 h60
  text "PER ORDER" at 13767.46,1599.76 h60
  text "XX MIL VIAS REQUIRE NON-CONDUCTIVE FILL AND PLANARIZE" at 11576.38,1394.82 h59
  text "XX MIL VIAS REQUIRE CONDUCTIVE FILL AND PLANARIZE" at 11584.38,1290.84 h60
  text "OUTER XX MIL TRACES REQUIRE 50 OHM SINGLE-ENDED IMPEDANCE" at 11583.39,1127.46 h58
  text "LAYER 2 & 3 (INNER LAYERS) XX MIL WIDE, XX MIL SPACE / TRACES REQUIRE 100 OHM DIFFERENTIAL IMPEDANCE" at 11575.39,891.74 h60
  text ".Layer_Name" at 577,-858.49 h60
M11 Gerber Information:
  lines w10: -292,-930.17 6308,-930.17 ; -292,-726.83 6310,-726.83 ; -292,-523.5 -292,-1133.5 3713,-1133.5 6310,-1133.5 6310,-523.5 -291.5,-523.5 -291.5,-1133.5 1284,-1133.5 ; 2173,-1133.5 2173,-523.5 ; 3440,-726.83 3440,-523.5 ; 4280,-726.83 4280,-523.5 ; 4902,-1140 4902,-937.17
  text "ALL ARTWORK VIEWED FROM TOP SIDE" at -228.5,-655.67 h60
  text "BOARD #:" at 2248,-655.67 h60
  text ".PRJ_Number" at 2793.5,-655.67 h60
  text "REV:" at 3638,-655.67 h60
  text ".PCB_Rev" at 3929.5,-655.67 h60
  text "SVN REV:" at 4476,-655.67 h60
  text ".VersionControl_RevNumber" at 4982,-655.67 h60
  text "LAYER NAME =" at -228.5,-858.49 h60
  text "TID #:" at 2248,-859 h60
  text ".TID" at 2793.5,-859 h60
  text "PLOT NAME =" at -228.5,-1064.34 h60
  text ".plot_File_Name" at 577,-1064.34 h60
  text "GENERATED    :" at 2250,-1064.34 h60
  text ".Print_Date" at 3119.5,-1064.34 h60
  text ".Print_Time" at 3848.5,-1064.34 h60
  text "TEXAS INSTRUMENTS" at 5113,-1064.34 h60
M12 Stackup:
  drawing of 191 lines, arcs and shapes, not listed
  text "Layer" at 9811.59,7492.44 h60
  text "Name" at 10221.51,7492.44 h60
  text "Material" at 11151.25,7492.44 h60
  text "Thickness" at 12011.02,7492.44 h60
  text "Constant" at 12660.85,7492.44 h60
  text "Board Layer Stack" at 13230.71,7492.44 h60
  text "1" at 9811.59,7372.44 h60
  text "Top Overlay" at 10221.51,7372.44 h60
  text "2" at 9811.59,7252.44 h60
  text "Top Solder" at 10221.51,7252.44 h60
  text "Solder Resist" at 11151.25,7252.44 h60
  text "0.40mil" at 12011.02,7252.44 h60
  text "3.5" at 12660.85,7252.44 h60
  text "3" at 9811.59,7132.44 h60
  text "Top Layer" at 10221.51,7132.44 h60
  text "Copper" at 11151.25,7132.44 h60
  text "2.80mil" at 12011.02,7132.44 h60
  text "4" at 9811.59,7012.44 h60
  text "Dielectric1" at 10221.51,7012.44 h60
  text "FR-4" at 11151.25,7012.44 h60
  text "56.40mil" at 12011.02,7012.44 h60
  text "4.8" at 12660.85,7012.44 h60
  text "5" at 9811.59,6892.44 h60
  text "Bottom Layer" at 10221.51,6892.44 h60
  text "Copper" at 11151.25,6892.44 h60
  text "2.80mil" at 12011.02,6892.44 h60
  text "6" at 9811.59,6772.44 h60
  text "Bottom Solder" at 10221.51,6772.44 h60
  text "Solder Resist" at 11151.25,6772.44 h60
  text "0.40mil" at 12011.02,6772.44 h60
  text "3.5" at 12660.85,6772.44 h60
  text "7" at 9811.59,6652.44 h60
  text "Bottom Overlay" at 10221.51,6652.44 h60
  text ".Layer_Name" at 577,-858.49 h60
M13 Component Bodies Top:
  text ".Layer_Name" at 577,-858.49 h60
M14 Component Bodies Bottom:
  text ".Layer_Name" at 577,-858.49 h60
M15 Courtyards Top:
  text ".Layer_Name" at 577,-858.49 h60
M16 Courtyards Bottom:
  text ".Layer_Name" at 577,-858.49 h60
Drill Drawing:
  circle w10: c2496.06,1384.09 r16.58
  circle w10: c2496.06,1384.09 r27.63
  circle w10: c2496.06,1135.45 r27.63
  lines w10: 2468.43,486.22 2523.69,486.22 2523.69,541.48 2468.43,541.48 2468.43,486.22 ; 2468.43,610.54 2468.43,624.36 2482.25,638.17 2468.43,651.98 2468.43,665.8 2482.25,665.8 2496.06,651.98 2509.87,665.8 2523.69,665.8 2523.69,651.98 2509.87,638.17 2523.69,624.36 2523.69,610.54 2509.87,610.54 2496.06,624.36 2482.25,610.54 2468.43,610.54 ; 2468.43,790.12 2523.69,790.12 2496.06,734.86 2468.43,790.12 ; 2468.43,873 2482.25,873 2482.25,859.18 2509.87,859.18 2509.87,873 2523.69,873 2523.69,900.62 2509.87,900.62 2509.87,914.44 2482.25,914.44 2482.25,900.62 2468.43,900.62 2468.43,873 ; 2468.43,1011.13 2496.06,983.5 2523.69,1011.13 2496.06,1038.76 2468.43,1011.13 ; 2468.43,1245.96 2482.25,1245.96 2496.06,1232.14 2509.87,1245.96 2523.69,1245.96 2509.87,1259.77 2523.69,1273.58 2509.87,1273.58 2496.06,1287.4 2482.25,1273.58 2468.43,1273.58 2482.25,1259.77 2468.43,1245.96 ; 2468.43,1480.78 2523.69,1480.78 2523.69,1536.04 2468.43,1536.04 2468.43,1480.78 ; 2479.48,1491.83 2512.64,1491.83 2512.64,1524.98 2479.48,1524.98 2479.48,1491.83
  lines w12: 2418.34,448.93 5649.83,448.93 ; 2418.34,1567.81 5649.83,1567.81 ; 2756.2,324.61 2756.2,1692.13 ; 3088.2,324.61 3088.2,1692.13 ; 3724.77,324.61 3724.77,1692.13 ; 3983.91,324.61 3983.91,1692.13 ; 4359.07,324.61 4359.07,1692.13 ; 5083.4,324.61 5083.4,1692.13 ; 2418.34,324.61 5649.83,324.61 5649.83,1692.13 2418.34,1692.13 2418.34,324.61
  text "Symbol" at 2492.93,1605.1 h72
  text "Quantity" at 2793.5,1605.1 h72
  text "Finished Hole Size" at 3125.5,1605.1 h72
  text "Plated" at 3762.06,1605.1 h72
  text "Hole Type" at 4021.2,1605.1 h72
  text "Drill Layer Pair" at 4396.36,1605.1 h72
  text "Hole Tolerance" at 5120.69,1605.1 h72
  text "14" at 2793.5,1480.78 h60
  text "10.00mil (0.254mm)" at 3125.5,1480.78 h60
  text "PTH" at 3762.06,1480.78 h60
  text "Round" at 4021.2,1480.78 h60
  text "Top Layer - Bottom Layer" at 4396.36,1480.78 h60
  text "51" at 2793.5,1356.46 h60
  text "12.00mil (0.305mm)" at 3125.5,1356.46 h60
  text "PTH" at 3762.06,1356.46 h60
  text "Round" at 4021.2,1356.46 h60
  text "Top Layer - Bottom Layer" at 4396.36,1356.46 h60
  text "3" at 2793.5,1232.14 h60
  text "14.00mil (0.356mm)" at 3125.5,1232.14 h60
  text "PTH" at 3762.06,1232.14 h60
  text "Round" at 4021.2,1232.14 h60
  text "Top Layer - Bottom Layer" at 4396.36,1232.14 h60
  text "1" at 2793.5,1107.82 h60
  text "16.00mil (0.406mm)" at 3125.5,1107.82 h60
  text "PTH" at 3762.06,1107.82 h60
  text "Round" at 4021.2,1107.82 h60
  text "Top Layer - Bottom Layer" at 4396.36,1107.82 h60
  text "5" at 2793.5,983.5 h60
  text "20.00mil (0.508mm)" at 3125.5,983.5 h60
  text "PTH" at 3762.06,983.5 h60
  text "Round" at 4021.2,983.5 h60
  text "Top Layer - Bottom Layer" at 4396.36,983.5 h60
  text "3" at 2793.5,859.18 h60
  text "25.00mil (0.635mm)" at 3125.5,859.18 h60
  text "PTH" at 3762.06,859.18 h60
  text "Round" at 4021.2,859.18 h60
  text "Top Layer - Bottom Layer" at 4396.36,859.18 h60
  text "3" at 2793.5,734.86 h60
  text "40.00mil (1.016mm)" at 3125.5,734.86 h60
  text "PTH" at 3762.06,734.86 h60
  text "Round" at 4021.2,734.86 h60
  text "Top Layer - Bottom Layer" at 4396.36,734.86 h60
  text "20" at 2793.5,610.54 h60
  text "40.16mil (1.020mm)" at 3125.5,610.54 h60
  text "PTH" at 3762.06,610.54 h60
  text "Round" at 4021.2,610.54 h60
  text "Top Layer - Bottom Layer" at 4396.36,610.54 h60
  text "3" at 2793.5,486.22 h60
  text "63.00mil (1.600mm)" at 3125.5,486.22 h60
  text "PTH" at 3762.06,486.22 h60
  text "Round" at 4021.2,486.22 h60
  text "Top Layer - Bottom Layer" at 4396.36,486.22 h60
  text "103 Total" at 2793.5,361.9 h60
  text ".Layer_Name" at 577,-858.49 h60
M17 Embedded Cavity:
  text ".Layer_Name" at 577,-858.49 h60
M18 Embedded Assembly:
  text ".Layer_Name" at 577,-858.49 h60
M19 Embedded Keepout:
  text ".Layer_Name" at 577,-858.49 h60

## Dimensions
0,-400 to 1000,-400 on M2 Board Dimensions
0,1700 to 0,0 on M2 Board Dimensions
1350,1700 to 0,0 on M2 Board Dimensions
